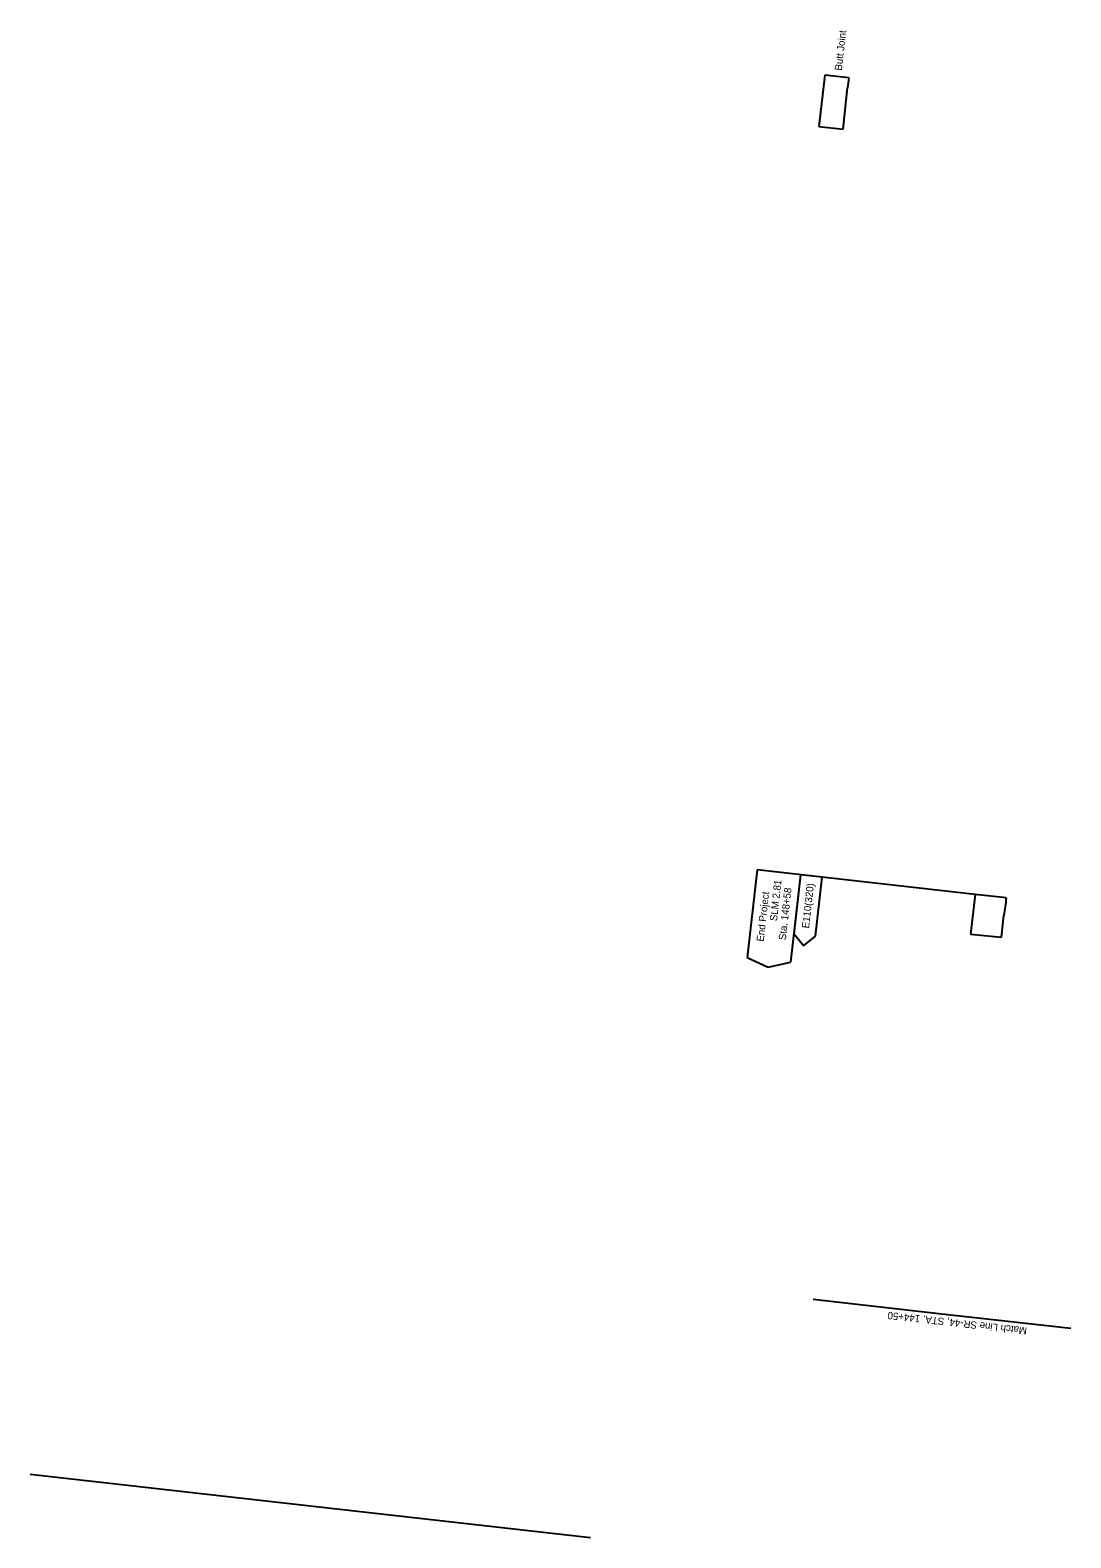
# Model space of a CAD drawing. Extents: x 2319604 to 2321967, y 627112 to 631396.
# Drawn here: x 2319604 to 2320607, y 627112 to 628564 of the extents above; entities that cross this region are included whole.
import ezdxf

# ---------------------------------------------------------------- set-up
doc = ezdxf.new("R2010")
doc.units = 0
for name, color, linetype in [('PV_P_Joint', 7, 'Continuous'), ('SC_Scratch1', 7, 'Continuous'), ('SH_Text', 7, 'Continuous'), ('TX_P_50', 7, 'Continuous')]:
    doc.layers.add(name, color=color, linetype=linetype)

msp = doc.modelspace()

# ---------------------------------------------------------------- linework, layer by layer
at = {"layer": 'PV_P_Joint'}
for p, q in [((2320369.8, 628521.1), (2320364.2, 628471.5)), ((2320393.1, 628518.3), (2320369.8, 628521.1)), ((2320387.4, 628468.9), (2320391.8, 628508.7)), ((2320364.2, 628471.5), (2320387.4, 628468.9)), ((2320514.8, 627731.9), (2320510.3, 627693.7)), ((2320544.7, 627728.6), (2320514.8, 627731.9)), ((2320540.2, 627690.7), (2320542.4, 627711.7)), ((2320510.3, 627693.7), (2320540.2, 627690.7))]:
    msp.add_line(p, q, dxfattribs=at)
for centre, major_axis, ratio in [((2320707, 628471.3), (-178.8, -262.9), 0.997947), ((2321099.1, 627645.1), (-315.3, -463.7), 0.999717)]:
    msp.add_ellipse(centre, major_axis=major_axis, ratio=ratio, start_param=5.160044, end_param=5.190378, dxfattribs=at)
at = {"layer": 'SC_Scratch1'}
msp.add_line((2320143.9, 627112.2), (2319604.1, 627173.1), dxfattribs=at)
at = {"layer": 'SH_Text'}
for q in [(2320339.9, 627694.1), (2320360.8, 627691.8)]:
    msp.add_line((2320349.2, 627682.5), q, dxfattribs=at)
for points in [[(2320360.8, 627691.8), (2320367.2, 627748.5), (2320346.3, 627750.9), (2320339.9, 627694.1)], [(2320606.9, 627313.7), (2320482.7, 627327.7), (2320358.5, 627341.7)]]:
    msp.add_lwpolyline(points, dxfattribs=at)
at = {"layer": 'TX_P_50'}
for p, q in [((2320304.6, 627755.6), (2320295.1, 627671.3)), ((2320346.3, 627750.9), (2320336.8, 627666.6))]:
    msp.add_line(p, q, dxfattribs=at)
for points in [[(2320514.8, 627731.9), (2320304.6, 627755.6)], [(2320295.1, 627671.3), (2320315.2, 627662), (2320336.8, 627666.6)]]:
    msp.add_lwpolyline(points, dxfattribs=at)

# ---------------------------------------------------------------- texts
at = {"layer": 'SH_Text'}
for s, rotation, p in [('E110(320)', 83.5594, (2320354.6, 627698.9)), ('Match Line SR-44, STA. 144+50', 173.5732, (2320564.9, 627314.9))]:
    msp.add_text(s, height=7, rotation=rotation, dxfattribs=at).set_placement(p)
at = {"layer": 'TX_P_50'}
for s, p in [('Butt Joint', (2320386.2, 628525.1)), (' SLM 2.81', (2320323.4, 627703.3)), (' Sta. 148+58', (2320331.9, 627685)), (' End Project', (2320310.6, 627683.6))]:
    msp.add_text(s, height=7, rotation=83.5594, dxfattribs=at).set_placement(p)

doc.saveas('drawing.dxf')
